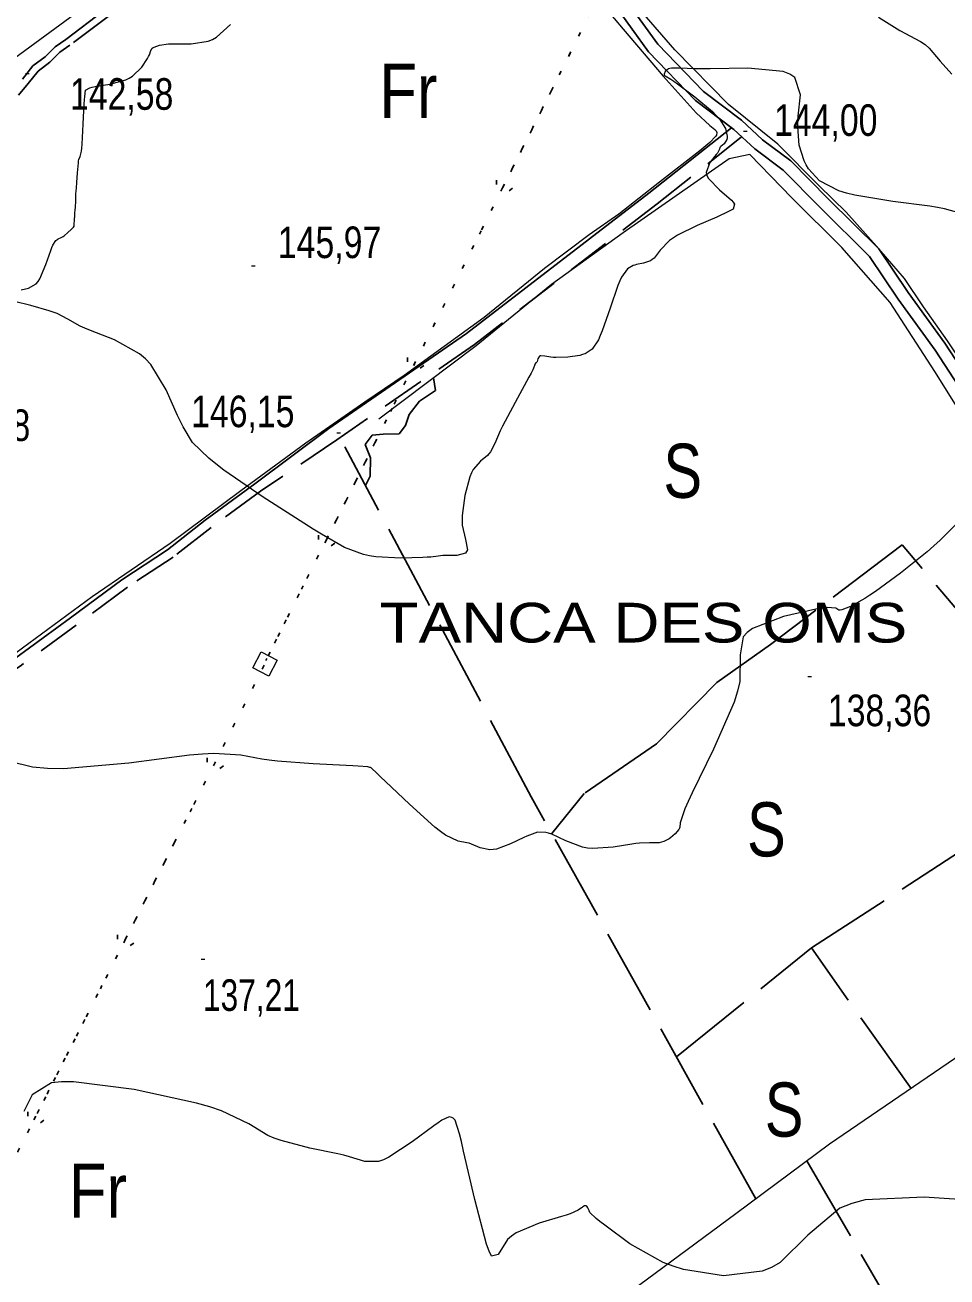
# Model space of a CAD drawing. Extents: x 483855 to 488461, y 4388206 to 4391419.
# Drawn here: x 484185.8 to 484441.1, y 4390434.8 to 4390781.6 of the extents above; entities that cross this region are included whole.
import ezdxf
from ezdxf.enums import TextEntityAlignment as Align

# ---------------------------------------------------------------- set-up
doc = ezdxf.new("R2010")
doc.units = 0
doc.header["$LTSCALE"] = 4
for name, pattern in [('DOTTED', [1.5, 0.3, -1.2]), ('LONG_DASHED', [7.5, 6, -1.5]), ('MEDIUM_DASHED', [4.5, 3, -1.5])]:
    doc.linetypes.add(name, pattern=pattern)
for name, color, linetype, lineweight in [('25', 7, 'LONG_DASHED', 25), ('36', 7, 'Continuous', 25), ('38', 7, 'Continuous', 25), ('43', 7, 'DOTTED', 25), ('51', 7, 'Continuous', 13), ('7', 7, 'Continuous', 13), ('9', 7, 'Continuous', 13)]:
    doc.layers.add(name, color=color, linetype=linetype, lineweight=lineweight)
doc.layers.add('31', color=7, linetype='Continuous')
doc.layers.add('5', color=7, linetype='Continuous')

msp = doc.modelspace()

# ---------------------------------------------------------------- linework, layer by layer
at = {"layer": '25'}
msp.add_line((484366.23, 4390495.79), (484403.59, 4390525.92), dxfattribs=at)
for points in [[(484298.96, 4390683.86), (484299.52, 4390680.35), (484295.06, 4390677.44), (484292.19, 4390673.71), (484291.19, 4390670.7), (484289.46, 4390668.34), (484285.03, 4390668.25), (484281.95, 4390668.01), (484280.03, 4390665.41), (484281.49, 4390661.72), (484281.41, 4390656.66), (484280.11, 4390654.09)], [(484388.2, 4390456.4), (484326.03, 4390567.8), (484274.41, 4390664.79)], [(484453.64, 4390608.14), (484428.75, 4390637.59), (484392.27, 4390609.97), (484377.42, 4390599.46), (484360.73, 4390582.46), (484340.69, 4390568.76), (484331.69, 4390557.68)], [(484431.19, 4390487.02), (484403.59, 4390525.92), (484475.75, 4390572.77), (484505.19, 4390595.33)], [(484402.34, 4390466.94), (484432.13, 4390415.62), (484485.66, 4390334.8)]]:
    msp.add_lwpolyline(points, dxfattribs=at)
at = {"layer": '36'}
for points in [[(484351.99, 4390788.86), (484361.05, 4390776.3), (484373.71, 4390763.18), (484384.21, 4390755.23), (484390.07, 4390749.85), (484397.95, 4390743.96), (484408.26, 4390733.46), (484422.3, 4390719.61), (484430.36, 4390707.54), (484440.59, 4390693.44), (484450.99, 4390677.52)], [(484349.41, 4390786.75), (484358.5, 4390774.16), (484371.5, 4390760.69), (484382.08, 4390752.68), (484387.94, 4390747.29), (484395.76, 4390741.45), (484405.91, 4390731.12), (484419.73, 4390717.48), (484427.63, 4390705.64), (484437.85, 4390691.55), (484448.23, 4390675.67)]]:
    msp.add_lwpolyline(points, dxfattribs=at)
at = {"layer": '38'}
for points in [[(484298.38, 4390855.03), (484284.66, 4390844.48), (484263.45, 4390827.61), (484250.72, 4390819.35), (484232.48, 4390806.42), (484219.57, 4390795.92), (484207.6, 4390785.54), (484197.08, 4390777.65), (484194.16, 4390775.6), (484191.43, 4390772.82), (484188.02, 4390770.33), (484185.14, 4390766.66)], [(484381.45, 4390753.17), (484358.54, 4390735.06), (484308.04, 4390696.12), (484269.98, 4390669.8)], [(484269.98, 4390669.8), (484249.43, 4390654.53), (484235.75, 4390644.4), (484225.25, 4390636.26), (484212.61, 4390627.93), (484198.4, 4390617.36), (484183.28, 4390606.34), (484164.98, 4390593.8), (484150.32, 4390583.28), (484138.17, 4390574.02), (484125.89, 4390565.6), (484114.39, 4390557.14)]]:
    msp.add_lwpolyline(points, dxfattribs=at)
at = {"layer": '38', "linetype": 'MEDIUM_DASHED'}
for points in [[(484299.91, 4390853), (484285.88, 4390842.88), (484264.62, 4390825.98), (484251.84, 4390817.69), (484233.7, 4390804.82), (484220.86, 4390794.38), (484208.86, 4390783.98), (484198.26, 4390776.03), (484195.47, 4390774.06), (484192.74, 4390771.29), (484189.43, 4390768.87), (484186.7, 4390765.4), (484184, 4390762.15)], [(484384.28, 4390750.65), (484360.86, 4390732.08), (484310.27, 4390693.07), (484272.13, 4390666.69)], [(484272.13, 4390666.69), (484251.01, 4390652.48), (484237.35, 4390642.38), (484226.81, 4390634.21), (484214.17, 4390625.87), (484199.98, 4390615.32), (484184.84, 4390604.29), (484166.54, 4390591.74), (484151.9, 4390581.24), (484139.74, 4390571.98), (484127.46, 4390563.55), (484114.38, 4390553.93)]]:
    msp.add_lwpolyline(points, dxfattribs=at)
at = {"layer": '43'}
for p, q in [((484336.75, 4390773.76), (484336.3, 4390772.87)), ((484332.05, 4390764.38), (484316.38, 4390733.08)), ((484316.38, 4390738.67), (484316.38, 4390733.08)), ((484320.85, 4390736.43), (484316.38, 4390733.08)), ((484312.12, 4390724.59), (484311.68, 4390723.69)), ((484307.42, 4390715.2), (484291.75, 4390683.9)), ((484291.75, 4390689.49), (484291.75, 4390683.9)), ((484296.23, 4390687.25), (484291.75, 4390683.9)), ((484287.5, 4390675.41), (484287.05, 4390674.51)), ((484282.8, 4390666.02), (484267.12, 4390634.72)), ((484267.13, 4390640.31), (484267.12, 4390634.72)), ((484271.6, 4390638.07), (484267.12, 4390634.72)), ((484262.87, 4390626.23), (484262.42, 4390625.33)), ((484258.17, 4390616.84), (484252.54, 4390605.6)), ((484252.08, 4390604.26), (484113.96, 4390331.46)), ((484252.08, 4390604.26), (484236.27, 4390573.03)), ((484236.3, 4390578.62), (484236.27, 4390573.03)), ((484240.76, 4390576.37), (484236.27, 4390573.03)), ((484231.98, 4390564.56), (484231.53, 4390563.67)), ((484227.24, 4390555.19), (484211.43, 4390523.97)), ((484211.45, 4390529.56), (484211.43, 4390523.97)), ((484215.92, 4390527.3), (484211.43, 4390523.97)), ((484207.14, 4390515.49), (484206.68, 4390514.6)), ((484202.39, 4390506.12), (484186.58, 4390474.9)), ((484186.61, 4390480.49), (484186.58, 4390474.9)), ((484191.07, 4390478.23), (484186.58, 4390474.9))]:
    msp.add_line(p, q, dxfattribs=at)
msp.add_lwpolyline([(484406.76, 4390911.49), (484366.53, 4390833.23), (484252.54, 4390605.6)], dxfattribs=at)
at = {"layer": '43', "linetype": 'Continuous', "lineweight": 13}
msp.add_lwpolyline([(484253.34, 4390601.22), (484248.9, 4390603.52), (484251.2, 4390607.96), (484255.64, 4390605.66)], close=True, dxfattribs=at)
at = {"layer": '51'}
for points in [[(484478.11, 4390639.7), (484451.1, 4390679.45), (484441.26, 4390694.15), (484434.68, 4390703.55), (484429.37, 4390711.41), (484422.4, 4390719.56), (484413.25, 4390729.74), (484405.75, 4390737.04), (484394.27, 4390748.6), (484380.61, 4390759.62), (484365.75, 4390774.77), (484347.67, 4390795.75), (484330.72, 4390817.1), (484312.38, 4390843.06)], [(484224.54, 4390803), (484180.2, 4390770.44), (484149.86, 4390698.23), (484127.82, 4390646.12), (484114.51, 4390615.64)], [(484336.53, 4390798.3), (484351.51, 4390780.49), (484362.52, 4390767.44), (484371.65, 4390757.25), (484375.45, 4390753.75), (484376.82, 4390752.7), (484377.23, 4390752.26), (484377.38, 4390751.83), (484377.29, 4390751.15), (484377.07, 4390750.76), (484375.48, 4390749.05), (484372.66, 4390746.77), (484361.51, 4390738.11), (484350.23, 4390729.22), (484342.02, 4390723.52), (484329.73, 4390714.13), (484312.96, 4390700.62), (484290.85, 4390684.51), (484279.94, 4390677.1), (484263.58, 4390665.82), (484245.63, 4390652.56), (484226.04, 4390638), (484204.41, 4390623.19), (484179.86, 4390605.12)], [(484516.61, 4390589.27), (484505.19, 4390595.33), (484497.46, 4390602.44), (484478.52, 4390625.06), (484449.72, 4390666.57), (484437.83, 4390685.61), (484425.42, 4390704.79), (484412.05, 4390720), (484398.22, 4390733.78), (484386.58, 4390745.76), (484380.8, 4390744.55), (484351.5, 4390724.02), (484331.65, 4390709.74), (484310.75, 4390692.75), (484283.85, 4390672.45)], [(484528.96, 4390555.31), (484496.29, 4390533.2), (484451.04, 4390500.57), (484408.63, 4390471.62), (484382.71, 4390452.3), (484342.62, 4390422.6), (484314.22, 4390402.75)]]:
    msp.add_lwpolyline(points, dxfattribs=at)
at = {"layer": '7'}
for p, q in [((484186, 4390768.23), (484187, 4390768.23)), ((484384.79, 4390752.21), (484385.79, 4390752.21)), ((484248.53, 4390714.93), (484249.53, 4390714.93)), ((484272.22, 4390668.66), (484273.22, 4390668.66)), ((484402.59, 4390601.16), (484403.59, 4390601.16)), ((484234.6, 4390522.87), (484235.6, 4390522.87))]:
    msp.add_line(p, q, dxfattribs=at)
at = {"layer": '9'}
for points in [[(484201.65, 4390748.62), (484201.94, 4390754.14), (484202.21, 4390759.74), (484202.28, 4390760.86), (484202.35, 4390761.79), (484202.59, 4390763.6), (484203.76, 4390764.22), (484204.41, 4390764.4), (484205.21, 4390764.59), (484209.29, 4390765.28), (484213.7, 4390766.42), (484214.71, 4390766.89), (484215.62, 4390767.42), (484218.15, 4390769.91), (484219.71, 4390772.39), (484220.01, 4390772.92), (484220.25, 4390773.39), (484220.65, 4390774.53), (484221.03, 4390775.18), (484221.27, 4390775.35), (484221.56, 4390775.51), (484223.06, 4390776.02), (484225.53, 4390776.37), (484226.43, 4390776.42), (484227.43, 4390776.45), (484231.8, 4390776.41), (484236.5, 4390777.13), (484237.71, 4390777.64), (484238.87, 4390778.29), (484242.73, 4390781.75)], [(484422.2, 4390783.75), (484428.13, 4390780.14), (484433.85, 4390777.08), (484435.12, 4390776.18), (484436.26, 4390775.24), (484439.28, 4390771.65), (484442.54, 4390768)], [(484371.41, 4390769.52), (484366.98, 4390769.66), (484364.88, 4390769.67), (484364.43, 4390769.59), (484364.05, 4390769.48), (484363.15, 4390768.77), (484362.84, 4390768), (484362.82, 4390767.85), (484362.84, 4390767.72), (484363.15, 4390767.51), (484364.71, 4390766.6), (484365.51, 4390766.04), (484366.48, 4390765.35), (484371.29, 4390761.75), (484376.17, 4390757.67), (484377.17, 4390756.69), (484378.02, 4390755.76), (484379.83, 4390752.94), (484380.27, 4390750.82), (484380.25, 4390750.34), (484380.17, 4390749.9), (484379.4, 4390748.72), (484378.5, 4390747.96), (484378.34, 4390747.8), (484378.23, 4390747.65), (484378.14, 4390747.25), (484377.82, 4390746.51), (484377.57, 4390746.15), (484377.24, 4390745.71), (484375.44, 4390743.54), (484374.48, 4390740.77), (484374.68, 4390739.96), (484375.08, 4390739.12), (484378.19, 4390735.95), (484381.47, 4390733.13), (484381.96, 4390732.51), (484382.29, 4390731.97), (484381.97, 4390730.64), (484379.54, 4390729.41), (484378.53, 4390728.95), (484377.37, 4390728.43), (484371.98, 4390726.08), (484366.55, 4390723.38), (484365.38, 4390722.64), (484364.34, 4390721.89), (484361.76, 4390719.22), (484360.03, 4390717.05), (484359.52, 4390716.62), (484359.01, 4390716.26), (484357.07, 4390715.62), (484355.17, 4390715.29), (484354.68, 4390715.13), (484354.21, 4390714.96), (484352.65, 4390714.09), (484351.04, 4390711.8), (484350.53, 4390710.71), (484349.99, 4390709.44), (484347.85, 4390703.21), (484345.68, 4390696.91), (484345.13, 4390695.58), (484344.61, 4390694.43), (484342.9, 4390691.78), (484340.91, 4390690.56), (484340.21, 4390690.31), (484339.44, 4390690.09), (484336.12, 4390689.61), (484332.87, 4390689.51), (484332.14, 4390689.52), (484331.48, 4390689.56), (484329.74, 4390689.85), (484328.7, 4390689.99), (484328.48, 4390689.94), (484328.29, 4390689.84), (484327.86, 4390689.15), (484327.63, 4390688.38), (484327.57, 4390688.24), (484327.51, 4390688.12), (484327.3, 4390687.95), (484327.15, 4390687.93), (484327.13, 4390687.91), (484327.12, 4390687.88), (484327.14, 4390687.71), (484326.43, 4390686.13), (484325.95, 4390685.2), (484325.35, 4390684.07), (484322.18, 4390678.21), (484318.8, 4390671.9), (484318.08, 4390670.47), (484317.44, 4390669.19), (484315.9, 4390665.73), (484314.72, 4390663.42), (484314.31, 4390662.86), (484313.86, 4390662.35), (484311.95, 4390660.77), (484309.97, 4390658.5), (484309.49, 4390657.55), (484309.03, 4390656.45), (484307.6, 4390651.29), (484306.87, 4390645.72), (484306.85, 4390644.35), (484306.92, 4390643.06)], [(484444.77, 4390729.48), (484440.43, 4390730.7), (484438.55, 4390731.05), (484436.38, 4390731.41), (484426.12, 4390732.74), (484415.62, 4390734.44), (484413.3, 4390735.03), (484411.23, 4390735.67), (484405.89, 4390738.41), (484402.79, 4390741.8), (484402.14, 4390742.86), (484401.57, 4390743.97), (484400.26, 4390748.38), (484399.87, 4390753.39), (484399.88, 4390754.88), (484399.94, 4390756.4), (484400.6, 4390762.24), (484398.98, 4390767.1), (484397.6, 4390768.01), (484395.81, 4390768.72), (484386.02, 4390769.7), (484375.54, 4390769.52), (484373.32, 4390769.51), (484371.41, 4390769.52)], [(484184.78, 4390708.24), (484186.82, 4390708.69), (484188.93, 4390709.92), (484189.46, 4390710.56), (484189.97, 4390711.34), (484191.63, 4390715.25), (484192.96, 4390719.18), (484193.27, 4390719.97), (484193.54, 4390720.63), (484194.31, 4390721.94), (484194.87, 4390722.32), (484195.01, 4390722.4), (484195.15, 4390722.47), (484195.63, 4390722.62), (484196.21, 4390722.9), (484196.42, 4390723.04), (484196.65, 4390723.22), (484197.66, 4390724.11), (484198.61, 4390724.99), (484198.8, 4390725.17), (484198.96, 4390725.31), (484199.29, 4390725.58), (484199.4, 4390725.94), (484199.43, 4390726.14), (484199.46, 4390726.39), (484199.53, 4390727.63), (484199.59, 4390728.88), (484199.6, 4390729.12), (484199.62, 4390729.32), (484199.66, 4390729.67), (484199.72, 4390730.22), (484199.74, 4390730.54), (484199.76, 4390730.93), (484199.85, 4390732.97), (484199.94, 4390735.01), (484199.96, 4390735.41), (484199.98, 4390735.73), (484200.04, 4390736.31), (484200.11, 4390737.05), (484200.14, 4390737.48), (484200.18, 4390738.01), (484200.35, 4390740.7), (484200.59, 4390743.41), (484200.66, 4390743.95), (484200.75, 4390744.39), (484201.1, 4390745.19), (484201.47, 4390746.68), (484201.56, 4390747.55), (484201.65, 4390748.62)], [(484306.92, 4390643.06), (484307.82, 4390639.07), (484308.32, 4390636.27), (484308.13, 4390635.74), (484307.8, 4390635.31), (484305.42, 4390634.67), (484302.61, 4390634.67), (484302.01, 4390634.65), (484301.49, 4390634.62), (484300.26, 4390634.46), (484298.22, 4390634.24), (484297.2, 4390634.18), (484295.97, 4390634.13), (484289.86, 4390633.93), (484282.96, 4390634.26), (484281.23, 4390634.54), (484279.58, 4390634.9), (484274.27, 4390636.88), (484267.9, 4390640.55), (484265.58, 4390641.97), (484263.01, 4390643.58), (484251.73, 4390650.85), (484240.91, 4390658.3), (484238.64, 4390660.02), (484236.69, 4390661.58), (484232.24, 4390665.99), (484229.65, 4390670.31), (484228.87, 4390671.82), (484228.06, 4390673.47), (484224.88, 4390680.56), (484220.65, 4390687.54), (484219.17, 4390689.11), (484217.56, 4390690.54), (484210.64, 4390694.39), (484203.92, 4390697), (484202.43, 4390697.63), (484201.11, 4390698.23), (484197.7, 4390700.09), (484194.69, 4390701.66), (484193.63, 4390702.08), (484192.47, 4390702.48), (484187.44, 4390703.89), (484182.94, 4390705.02)], [(484445.13, 4390644.82), (484439.3, 4390638.92), (484437.52, 4390637.29), (484435.65, 4390635.65), (484428.27, 4390629.73), (484421.37, 4390624.7), (484419.8, 4390623.63), (484418.37, 4390622.7)], [(484418.37, 4390622.7), (484414.47, 4390620.49), (484412.05, 4390619.63), (484411.57, 4390619.54), (484411.17, 4390619.53), (484410.39, 4390620.03), (484408.01, 4390620.26), (484406.61, 4390620.06), (484404.87, 4390619.76), (484395.9, 4390617.74), (484387.31, 4390614.44), (484385.82, 4390613.33), (484384.7, 4390612.14), (484383.88, 4390607.11), (484383.78, 4390599.71), (484383.11, 4390597.03), (484382.18, 4390594.06), (484376.52, 4390581.04), (484370.57, 4390568.88), (484369.45, 4390566.46), (484368.56, 4390564.46), (484367.28, 4390560.62), (484367.19, 4390559.43), (484367.06, 4390559.1), (484366.88, 4390558.76), (484365.85, 4390557.52), (484364.56, 4390556.43), (484364.22, 4390556.19), (484363.88, 4390555.97), (484362.71, 4390555.4), (484361.42, 4390555.1), (484361.01, 4390555.06), (484360.57, 4390555.03), (484358.77, 4390555.06), (484356.04, 4390554.97), (484355.01, 4390554.86), (484353.85, 4390554.71), (484348.7, 4390553.88), (484343.08, 4390553.48), (484341.63, 4390553.62), (484340.23, 4390553.85), (484335.55, 4390555.58), (484331.7, 4390557.41), (484330.82, 4390557.72), (484330.02, 4390557.94), (484327.78, 4390558.01), (484325.57, 4390557.2), (484324.79, 4390556.87), (484323.94, 4390556.49), (484320.23, 4390554.75), (484316.39, 4390553.34), (484315.46, 4390553.18), (484314.58, 4390553.11), (484311.87, 4390553.7), (484309.51, 4390554.72), (484308.85, 4390554.93), (484308.2, 4390555.1), (484305.82, 4390555.49), (484302.29, 4390557.17), (484300.9, 4390558.16), (484299.35, 4390559.39), (484292.26, 4390565.73), (484285.63, 4390572.06), (484284.36, 4390573.27), (484283.33, 4390574.24), (484281.65, 4390575.82), (484281.47, 4390575.9), (484281.38, 4390575.92), (484281.27, 4390575.95), (484280.75, 4390576.09), (484278.06, 4390576.32), (484276.58, 4390576.41), (484274.78, 4390576.51), (484265.64, 4390576.98), (484255.75, 4390577.68), (484253.48, 4390577.93), (484251.4, 4390578.2), (484245.59, 4390579.37), (484238.09, 4390579.83), (484234.96, 4390579.65), (484231.36, 4390579.34), (484214.55, 4390577.13), (484196.44, 4390575.57), (484192.03, 4390575.68), (484187.88, 4390576.02), (484175.04, 4390579.18)], [(484411.52, 4390453.84), (484402.57, 4390446.39), (484394.99, 4390438.83), (484392.54, 4390437.44), (484389.94, 4390436.37), (484379.26, 4390435.07), (484368.18, 4390436.87), (484365.32, 4390437.75), (484362.55, 4390438.8), (484353.33, 4390443.98), (484346.38, 4390449.12), (484345.04, 4390450.14), (484343.97, 4390450.99), (484342.21, 4390452.6), (484342.09, 4390453.1), (484342.03, 4390453.24), (484341.97, 4390453.39), (484341.7, 4390453.96), (484341.37, 4390454.4), (484341.27, 4390454.47), (484341.18, 4390454.51), (484340.81, 4390454.48), (484340.31, 4390454.18), (484340.12, 4390454.06), (484339.92, 4390453.93), (484339.04, 4390453.31), (484336.76, 4390452.3), (484335.68, 4390451.93), (484334.4, 4390451.51), (484328.18, 4390449.65), (484321.88, 4390447.03), (484320.56, 4390446.13), (484319.42, 4390445.16), (484316.84, 4390441.03), (484315, 4390440.56), (484314.33, 4390441.9), (484313.6, 4390443.86), (484310.37, 4390456.25), (484307.3, 4390469.67), (484306.67, 4390472.29), (484306.14, 4390474.43), (484304.99, 4390478.2), (484304.4, 4390478.76), (484304.22, 4390478.87), (484304.04, 4390478.97), (484303.3, 4390479.19), (484301.24, 4390478.19), (484300.23, 4390477.52), (484299.02, 4390476.68), (484293.03, 4390472.21), (484286.61, 4390467.97), (484285.12, 4390467.27), (484283.76, 4390466.78), (484279.89, 4390466.73), (484275.71, 4390468.1), (484274.16, 4390468.51), (484272.42, 4390468.92), (484264.72, 4390470.51), (484256.75, 4390472.55), (484254.85, 4390473.25), (484253.08, 4390474.01), (484247.8, 4390477.21), (484240.24, 4390480.85), (484237.03, 4390481.88), (484233.35, 4390482.92), (484216.03, 4390486.73), (484199.26, 4390488.86), (484195.92, 4390488.83), (484193.14, 4390488.53), (484187.83, 4390485.25), (484185.5, 4390480.66)], [(484450.15, 4390455.89), (484434.83, 4390456.92), (484418.51, 4390456.12), (484414.83, 4390455.14), (484411.52, 4390453.84)]]:
    msp.add_lwpolyline(points, dxfattribs=at)

# ---------------------------------------------------------------- texts
at = {"layer": '31'}
for s, width, p in [('Fr', 0.85, (484292.01, 4390755.89)), ('S', 0.8, (484367.97, 4390650.63)), ('S', 0.8, (484391.14, 4390551.29)), ('S', 0.8, (484396.04, 4390473.66)), ('Fr', 0.85, (484206.05, 4390451.19))]:
    msp.add_text(s, height=15, dxfattribs=dict(at, width=width)).set_placement(p, align=Align.CENTER)
at = {"layer": '5', "width": 1.2}
msp.add_text('TANCA DES OMS', height=11, dxfattribs=at).set_placement((484430.17, 4390610.55), align=Align.RIGHT)
at = {"layer": '7'}
for s, width, p in [('142,58', 0.8, (484198.27, 4390758.14)), ('144,00', 0.8, (484393.26, 4390750.9)), ('145,97', 0.8, (484255.85, 4390717.05)), ('146,15', 0.8, (484231.81, 4390670.21)), ('141,68', 0.8, (484158.65, 4390666.38)), ('138,36', 0.8, (484408.16, 4390587.37)), ('137,21', 0.75, (484235.1, 4390508.5))]:
    msp.add_text(s, height=8.75, dxfattribs=dict(at, width=width)).set_placement(p)

doc.saveas('drawing.dxf')
